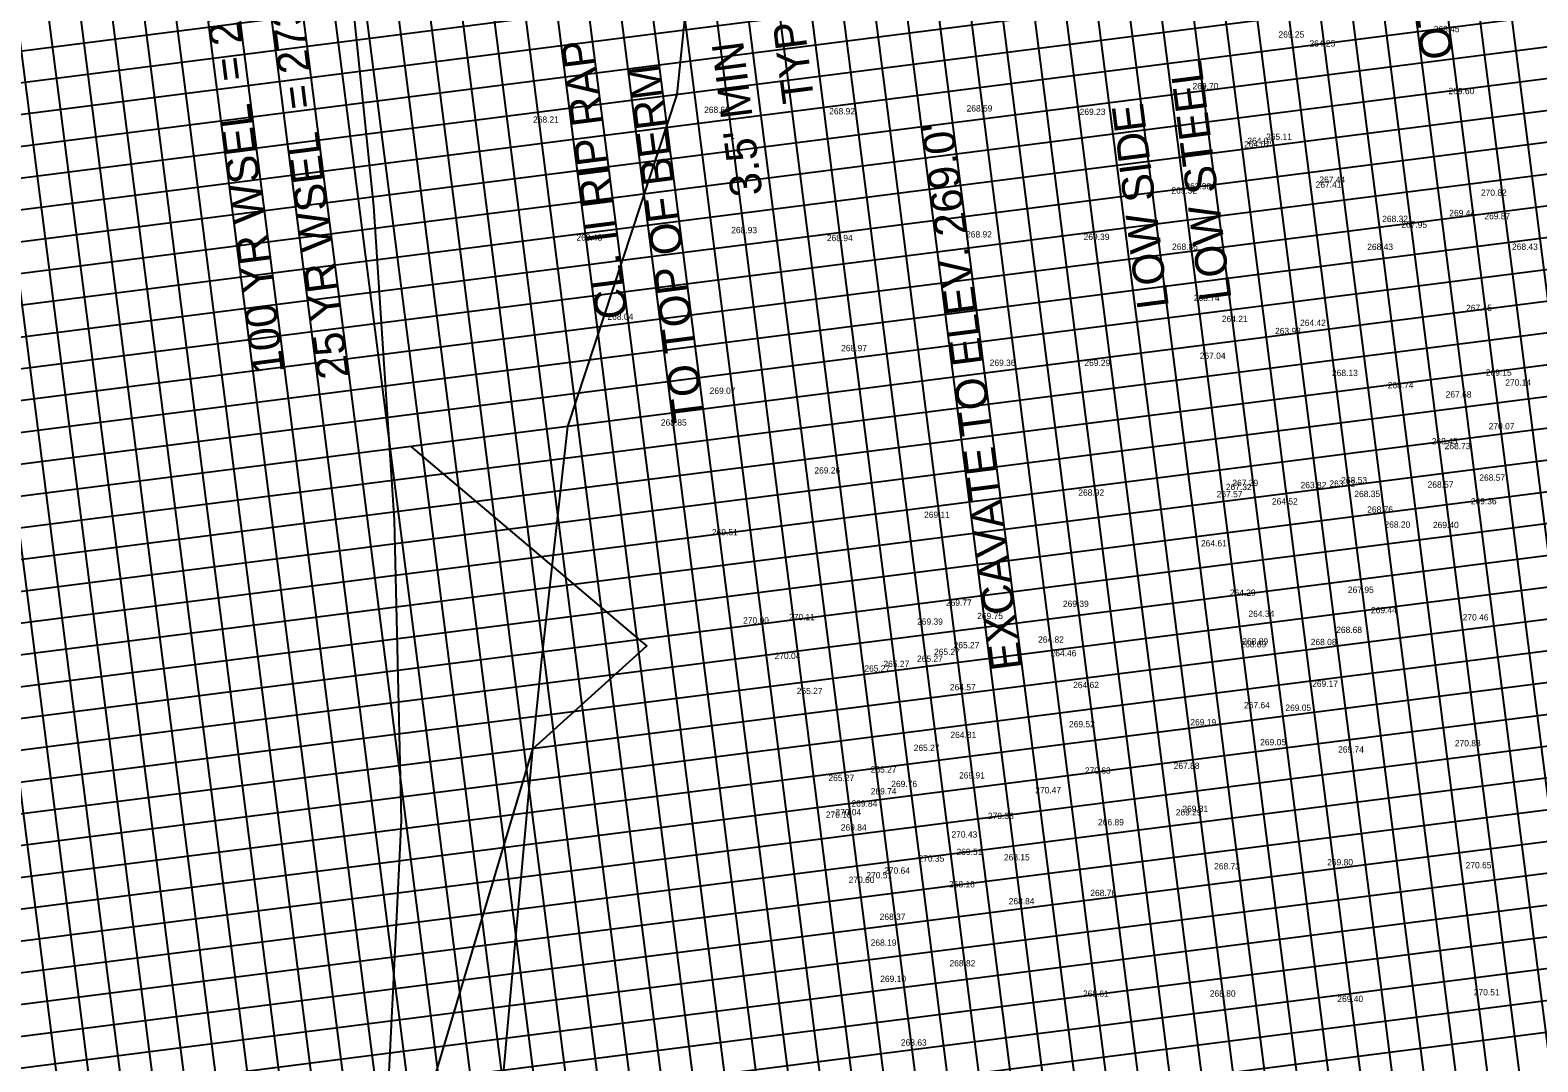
# Model space of a CAD drawing. Extents: x 2166991 to 2168450, y 842134 to 844444.
# Drawn here: x 2167712.5 to 2167951.5, y 843150.2 to 843313.8 of the extents above; entities that cross this region are included whole.
import ezdxf

# ---------------------------------------------------------------- set-up
doc = ezdxf.new("R2010")
doc.units = 0
for name, color, linetype in [('Exist Hydrographic Top of Bank', 7, 'Continuous'), ('Exist Plan Preparation Drainage Notes Label', 7, 'Continuous'), ('Prop Drainage Structure Drop Inlet Grate 2 Narrow Slots and Flat Grates 840 29 CELL', 7, 'Continuous'), ('Prop Erosion Rip Rap Class II', 7, 'Continuous'), ('Prop Plan Preparation Excavation Hatching', 7, 'Continuous'), ('Prop Plan Preparation Excavation Hatching Label', 7, 'Continuous'), ('Scratch_Level_3', 7, 'Continuous')]:
    doc.layers.add(name, color=color, linetype=linetype)

msp = doc.modelspace()

# ---------------------------------------------------------------- linework, layer by layer
at = {"layer": 'Exist Hydrographic Top of Bank'}
msp.add_line((2167823.97, 843296.65), (2167823.97, 843296.58), dxfattribs=at)
at = {"layer": 'Exist Plan Preparation Drainage Notes Label'}
for p, q in [((2167983.55, 842795.83), (2167825.17, 844035.76)), ((2167933.95, 842789.5), (2167775.57, 844029.42)), ((2167884.35, 842783.16), (2167725.98, 844023.09)), ((2167834.76, 842776.83), (2167676.38, 844016.75)), ((2167995.26, 842822.53), (2167843.22, 844012.86)), ((2168000.22, 842823.16), (2167848.18, 844013.49)), ((2168005.18, 842823.8), (2167853.14, 844014.13)), ((2168010.14, 842824.43), (2167858.1, 844014.76)), ((2167785.16, 842770.49), (2167626.78, 844010.42)), ((2167975.42, 842820), (2167823.38, 844010.33)), ((2167985.34, 842821.26), (2167833.3, 844011.59)), ((2167990.3, 842821.9), (2167838.26, 844012.23)), ((2167955.58, 842817.46), (2167803.54, 844007.79)), ((2167960.54, 842818.1), (2167808.5, 844008.43)), ((2167965.5, 842818.73), (2167813.46, 844009.06)), ((2167970.46, 842819.36), (2167818.42, 844009.69)), ((2167935.74, 842814.93), (2167783.7, 844005.26)), ((2167940.7, 842815.56), (2167788.66, 844005.89)), ((2167945.66, 842816.2), (2167793.62, 844006.52)), ((2167950.62, 842816.83), (2167798.58, 844007.16)), ((2167920.86, 842813.03), (2167768.82, 844003.36)), ((2167925.82, 842813.66), (2167773.78, 844003.99)), ((2167901.03, 842810.49), (2167748.98, 844000.82)), ((2167905.98, 842811.13), (2167753.94, 844001.46)), ((2167910.94, 842811.76), (2167758.9, 844002.09)), ((2167915.9, 842812.39), (2167763.86, 844002.72)), ((2167886.15, 842808.59), (2167734.11, 843998.92)), ((2167891.11, 842809.23), (2167739.06, 843999.56)), ((2167896.07, 842809.86), (2167744.02, 844000.19)), ((2167861.35, 842805.43), (2167709.31, 843995.76)), ((2167866.31, 842806.06), (2167714.27, 843996.39)), ((2167871.27, 842806.69), (2167719.23, 843997.02)), ((2167876.23, 842807.33), (2167724.19, 843997.66)), ((2167846.47, 842803.53), (2167694.43, 843993.85)), ((2167851.43, 842804.16), (2167699.39, 843994.49)), ((2167856.39, 842804.79), (2167704.35, 843995.12)), ((2167826.63, 842800.99), (2167674.59, 843991.32)), ((2167836.55, 842802.26), (2167684.51, 843992.59)), ((2167841.51, 842802.89), (2167689.47, 843993.22)), ((2167806.79, 842798.46), (2167654.75, 843988.79)), ((2167811.75, 842799.09), (2167659.71, 843989.42)), ((2167816.71, 842799.72), (2167664.67, 843990.05)), ((2167821.67, 842800.36), (2167669.63, 843990.69)), ((2167786.95, 842795.92), (2167634.91, 843986.25)), ((2167791.91, 842796.56), (2167639.87, 843986.89)), ((2167796.87, 842797.19), (2167644.83, 843987.52)), ((2167801.83, 842797.82), (2167649.79, 843988.15)), ((2167772.07, 842794.02), (2167620.03, 843984.35)), ((2167777.03, 842794.66), (2167624.99, 843984.99)), ((2167762.15, 842792.76), (2167610.11, 843983.09)), ((2167767.11, 842793.39), (2167615.07, 843983.72)), ((2168162.48, 843368.11), (2167666.51, 843304.76)), ((2168163.11, 843363.15), (2167667.14, 843299.8)), ((2168163.75, 843358.2), (2167667.78, 843294.84)), ((2168164.38, 843353.24), (2167668.41, 843289.89)), ((2168165.02, 843348.28), (2167644.25, 843281.76)), ((2168165.65, 843343.32), (2167669.68, 843279.97)), ((2168166.28, 843338.36), (2167670.31, 843275.01)), ((2168166.92, 843333.4), (2167670.95, 843270.05)), ((2168167.55, 843328.44), (2167671.58, 843265.09)), ((2168168.18, 843323.48), (2167672.21, 843260.13)), ((2168168.82, 843318.52), (2167672.85, 843255.17)), ((2168169.45, 843313.56), (2167673.48, 843250.21)), ((2168170.08, 843308.6), (2167674.11, 843245.25)), ((2168170.72, 843303.64), (2167674.75, 843240.29)), ((2168171.35, 843298.68), (2167650.58, 843232.16)), ((2168171.98, 843293.72), (2167676.01, 843230.37)), ((2168172.62, 843288.76), (2167676.65, 843225.41)), ((2168173.25, 843283.8), (2167677.28, 843220.45)), ((2168173.88, 843278.84), (2167677.91, 843215.49)), ((2168174.52, 843273.88), (2167678.55, 843210.53)), ((2168175.15, 843268.92), (2167679.18, 843205.57)), ((2168175.78, 843263.96), (2167679.81, 843200.61)), ((2168176.42, 843259), (2167680.45, 843195.65)), ((2168177.05, 843254.04), (2167681.08, 843190.69)), ((2168177.69, 843249.08), (2167656.92, 843182.56)), ((2168178.32, 843244.12), (2167682.35, 843180.77)), ((2168178.95, 843239.16), (2167682.98, 843175.81)), ((2168179.59, 843234.2), (2167683.62, 843170.85)), ((2168180.22, 843229.24), (2167684.25, 843165.89)), ((2168180.85, 843224.28), (2167684.88, 843160.93)), ((2168181.49, 843219.32), (2167685.52, 843155.97)), ((2168182.12, 843214.36), (2167686.15, 843151.01)), ((2168182.75, 843209.4), (2167686.78, 843146.05)), ((2168183.39, 843204.44), (2167687.42, 843141.09)), ((2168184.02, 843199.48), (2167663.25, 843132.97)), ((2168184.65, 843194.53), (2167688.68, 843131.17)), ((2168185.29, 843189.57), (2167689.32, 843126.21)), ((2168185.92, 843184.61), (2167689.95, 843121.26))]:
    msp.add_line(p, q, dxfattribs=at)
at = {"layer": 'Prop Drainage Structure Drop Inlet Grate 2 Narrow Slots and Flat Grates 840 29 CELL'}
msp.add_lwpolyline([(2167757.79, 842963.56), (2167770.55, 842995.45), (2167773.98, 843046.3), (2167776.61, 843068.3), (2167777.35, 843097.13), (2167787.62, 843148.85), (2167792.18, 843199.84), (2167793.61, 843214.01), (2167797.76, 843250.96), (2167815.06, 843303.58), (2167817.99, 843332.01), (2167815.17, 843366.59)], dxfattribs=at)
at = {"layer": 'Prop Plan Preparation Excavation Hatching'}
msp.add_lwpolyline([(2167764.31, 843094.3), (2167776.57, 843147.44), (2167792.18, 843199.84), (2167810.26, 843216.13), (2167772.9, 843247.78)], dxfattribs=at)
at = {"layer": 'Prop Plan Preparation Excavation Hatching Label'}
msp.add_lwpolyline([(2167751.39, 842824.91), (2167752.39, 842844.74), (2167753.95, 842874.72), (2167755.15, 842897.27), (2167757.06, 842927.31), (2167757.92, 842945.41), (2167760.09, 842975.47), (2167761.25, 842993.97), (2167762.76, 843023.98), (2167763.76, 843044.55), (2167765.23, 843074.51), (2167766.29, 843095.78), (2167768.15, 843125.8), (2167769.02, 843139.96), (2167770.48, 843169.95), (2167771.39, 843188.46), (2167770.67, 843218.15), (2167770.25, 843236.07), (2167768.33, 843265.68), (2167767.02, 843285.86), (2167763.97, 843315.19), (2167760.56, 843343.94)], dxfattribs=at)

# ---------------------------------------------------------------- texts
at = {"layer": 'Exist Hydrographic Top of Bank'}
for s, p in [('TYP', (2167836.81, 843302.55)), ('CL. II RIP RAP', (2167807.28, 843268.29)), ("3.5' MIN", (2167828.62, 843287.77)), ('TO TOP OF BERM', (2167819.45, 843251.91)), ('LOW STEEL', (2167902.96, 843271.21)), ('LOW SIDE', (2167893.04, 843269.94)), ("EXCAVATE TO ELEV. 269.0'", (2167869.83, 843212.58))]:
    msp.add_text(s, height=5, rotation=97.279, dxfattribs=at).set_placement(p)
at = {"layer": 'Prop Erosion Rip Rap Class II'}
for s, p in [('OT SCOUR', (2167938.1, 843309.47)), ("100 YR WSEL  = 275.59'", (2167752.81, 843259.57)), ("25 YR WSEL  = 273.7'", (2167763.11, 843258.81))]:
    msp.add_text(s, height=5, rotation=97.279, dxfattribs=at).set_placement(p)
at = {"layer": 'Scratch_Level_3'}
for s, p in [('269.25', (2167910.39, 843312.61)), ('264.25', (2167915.31, 843311.19)), ('268.45', (2167935, 843313.47)), ('269.70', (2167896.78, 843304.42)), ('269.60', (2167937.35, 843303.64)), ('268.65', (2167819.35, 843300.66)), ('268.92', (2167839.18, 843300.43)), ('268.59', (2167860.96, 843300.89)), ('269.23', (2167878.88, 843300.35)), ('268.21', (2167792.23, 843299.11)), ('264.07', (2167904.95, 843295.18)), ('264.07', (2167905.46, 843295.75)), ('265.11', (2167908.44, 843296.39)), ('269.52', (2167893.42, 843287.88)), ('263.98', (2167895.64, 843288.54)), ('267.41', (2167916.29, 843288.81)), ('267.44', (2167916.88, 843289.58)), ('270.82', (2167942.49, 843287.52)), ('268.32', (2167926.84, 843283.36)), ('269.44', (2167937.48, 843284.29)), ('269.87', (2167943.04, 843283.8)), ('268.43', (2167799.11, 843280.41)), ('268.93', (2167823.65, 843281.59)), ('268.94', (2167838.81, 843280.33)), ('268.92', (2167860.88, 843280.91)), ('269.39', (2167879.51, 843280.51)), ('267.95', (2167929.86, 843282.45)), ('268.86', (2167893.53, 843278.95)), ('268.43', (2167924.47, 843278.93)), ('268.43', (2167947.42, 843278.95)), ('268.74', (2167896.97, 843270.83)), ('267.45', (2167940.14, 843269.24)), ('268.04', (2167804.03, 843267.85)), ('264.21', (2167901.42, 843267.49)), ('264.42', (2167913.82, 843266.89)), ('263.93', (2167909.85, 843265.58)), ('268.97', (2167841.07, 843262.88)), ('267.04', (2167897.92, 843261.66)), ('269.36', (2167864.62, 843260.55)), ('269.29', (2167879.63, 843260.54)), ('268.13', (2167918.88, 843258.93)), ('269.15', (2167943.27, 843258.98)), ('268.74', (2167927.71, 843256.98)), ('270.14', (2167946.35, 843257.41)), ('269.07', (2167820.23, 843256.11)), ('267.68', (2167936.9, 843255.53)), ('268.85', (2167812.5, 843251.08)), ('270.07', (2167943.72, 843250.48)), ('268.45', (2167934.7, 843248.09)), ('268.73', (2167936.74, 843247.34)), ('269.26', (2167836.83, 843243.48)), ('268.53', (2167920.35, 843241.93)), ('268.57', (2167942.23, 843242.33)), ('268.92', (2167878.67, 843239.96)), ('267.57', (2167900.6, 843239.71)), ('267.32', (2167902.06, 843240.85)), ('267.39', (2167903.09, 843241.49)), ('263.82', (2167913.9, 843241.15)), ('263.82', (2167918.47, 843241.38)), ('268.35', (2167922.42, 843239.74)), ('268.57', (2167934.04, 843241.23)), ('264.52', (2167909.36, 843238.56)), ('268.76', (2167924.46, 843237.26)), ('269.36', (2167940.89, 843238.58)), ('269.11', (2167854.22, 843236.44)), ('268.20', (2167927.2, 843234.88)), ('269.40', (2167934.88, 843234.82)), ('269.51', (2167820.59, 843233.67)), ('264.61', (2167898.11, 843231.91)), ('264.29', (2167902.69, 843224.08)), ('267.95', (2167921.41, 843224.55)), ('269.77', (2167857.68, 843222.5)), ('269.75', (2167862.63, 843220.39)), ('269.39', (2167876.23, 843222.32)), ('264.34', (2167905.64, 843220.74)), ('269.44', (2167925.06, 843221.32)), ('270.00', (2167825.53, 843219.68)), ('270.11', (2167832.82, 843220.22)), ('269.39', (2167853.11, 843219.49)), ('268.68', (2167919.55, 843218.19)), ('270.46', (2167939.6, 843220.17)), ('265.27', (2167858.9, 843215.77)), ('264.82', (2167872.29, 843216.65)), ('268.89', (2167904.37, 843215.9)), ('268.89', (2167904.66, 843216.36)), ('268.08', (2167915.51, 843216.26)), ('270.04', (2167830.52, 843214.05)), ('265.27', (2167853.1, 843213.61)), ('265.27', (2167855.8, 843214.69)), ('264.46', (2167874.27, 843214.48)), ('265.27', (2167844.75, 843212.07)), ('265.27', (2167847.78, 843212.78)), ('265.27', (2167834.03, 843208.49)), ('264.57', (2167858.31, 843209.09)), ('264.62', (2167877.85, 843209.44)), ('269.17', (2167915.74, 843209.64)), ('267.64', (2167904.94, 843206.24)), ('269.05', (2167911.49, 843205.84)), ('264.81', (2167858.4, 843201.53)), ('269.52', (2167877.19, 843203.23)), ('269.19', (2167896.43, 843203.53)), ('265.27', (2167852.58, 843199.48)), ('269.05', (2167907.5, 843200.37)), ('269.74', (2167919.85, 843199.22)), ('270.88', (2167938.36, 843200.21)), ('267.88', (2167893.78, 843196.62)), ('265.27', (2167839.06, 843194.7)), ('265.27', (2167845.77, 843196.05)), ('269.91', (2167859.77, 843195.11)), ('270.63', (2167879.71, 843195.88)), ('269.74', (2167845.76, 843192.58)), ('269.76', (2167849.02, 843193.75)), ('270.47', (2167871.85, 843192.76)), ('270.04', (2167840.16, 843189.28)), ('269.84', (2167842.71, 843190.65)), ('269.29', (2167894.11, 843189.25)), ('269.31', (2167895.16, 843189.81)), ('270.18', (2167838.64, 843188.88)), ('270.38', (2167864.34, 843188.68)), ('266.89', (2167881.8, 843187.68)), ('269.84', (2167841.02, 843186.85)), ('270.43', (2167858.56, 843185.74)), ('269.51', (2167859.36, 843182.97)), ('268.15', (2167866.88, 843182.12)), ('270.64', (2167847.89, 843180.01)), ('270.35', (2167853.33, 843181.92)), ('268.73', (2167900.2, 843180.69)), ('269.80', (2167918.12, 843181.33)), ('270.65', (2167940.07, 843180.86)), ('270.60', (2167842.26, 843178.54)), ('270.51', (2167845.07, 843179.27)), ('268.16', (2167858.17, 843177.84)), ('268.84', (2167867.63, 843175.16)), ('268.76', (2167880.57, 843176.46)), ('268.37', (2167847.18, 843172.69)), ('268.19', (2167845.75, 843168.58)), ('268.82', (2167858.25, 843165.31)), ('269.10', (2167847.27, 843162.85)), ('270.51', (2167941.36, 843160.71)), ('268.61', (2167879.41, 843160.49)), ('268.80', (2167899.51, 843160.51)), ('269.40', (2167919.73, 843159.66)), ('268.63', (2167850.54, 843152.75))]:
    msp.add_text(s, height=1, dxfattribs=at).set_placement(p)

doc.saveas('drawing.dxf')
